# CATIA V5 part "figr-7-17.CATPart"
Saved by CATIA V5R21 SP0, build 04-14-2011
Part number: Part2
Bounding box of the stored display mesh (mm): x -50 to 50, y -65 to 65, z 0 to 28
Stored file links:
  D:\CATIA V5R21 E-RESOURCES\CATIA-V5R21\catia-v5r21-prt\c07-catia-v5r20-prt\c07-catia-v5r21-figr-7-17.CATPart
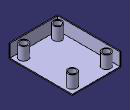
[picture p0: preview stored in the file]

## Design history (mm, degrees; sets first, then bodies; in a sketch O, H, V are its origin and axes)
Body1 (main body)
  Sketch1 on xy-plane, origin (0, 0, 0), H (1, 0, 0), V (0, 1, 0)
    line L1 (-50, 65) -> (50, 65)
    line L2 (50, 65) -> (50, -65)
    line L3 (50, -65) -> (-50, -65)
    line L4 (-50, -65) -> (-50, 65)
    axis line L5 (50, -65) -> (-50, 65)
    length L3 = 100
    length L2 = 130
    horizontal: L1 H, L3 H
    vertical: L2 V, L4 V
    midpoint: O L5
  Pad1: profile Sketch1, direction (0, 0, 1), length 28
  Sketch2 on face of Pad1, origin (25.9302, -33.7092, 28), H (1, 0, 0), V (0, 1, 0)
    point P1 (9.0698, -16.2908)
    reference projected line E1 (-75.9302, -31.2908) -> (24.0698, -31.2908) from edge [face of Pad1 | face of Pad1]
    reference projected line E2 (24.0698, -31.2908) -> (24.0698, 98.7092) from edge [face of Pad1 | face of Pad1]
    distance P1 E1 = 15
    distance P1 E2 = 15
  Hole1: placed by Sketch2, at (35, -50, 28) direction (0, 0, -1), diameter 14, through (limit type 3)
  RectPattern1: of Hole1, direction 1 instances 2, spacing 100, along edge [face of Pad1 | face of Pad1], direction 2 instances 2, spacing 70, along edge [face of Pad1 | face of Pad1]
  Shell1: ExtOffset 0, Face (face of Pad1; face of Pad1; face of Pad1), IntOffset 2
